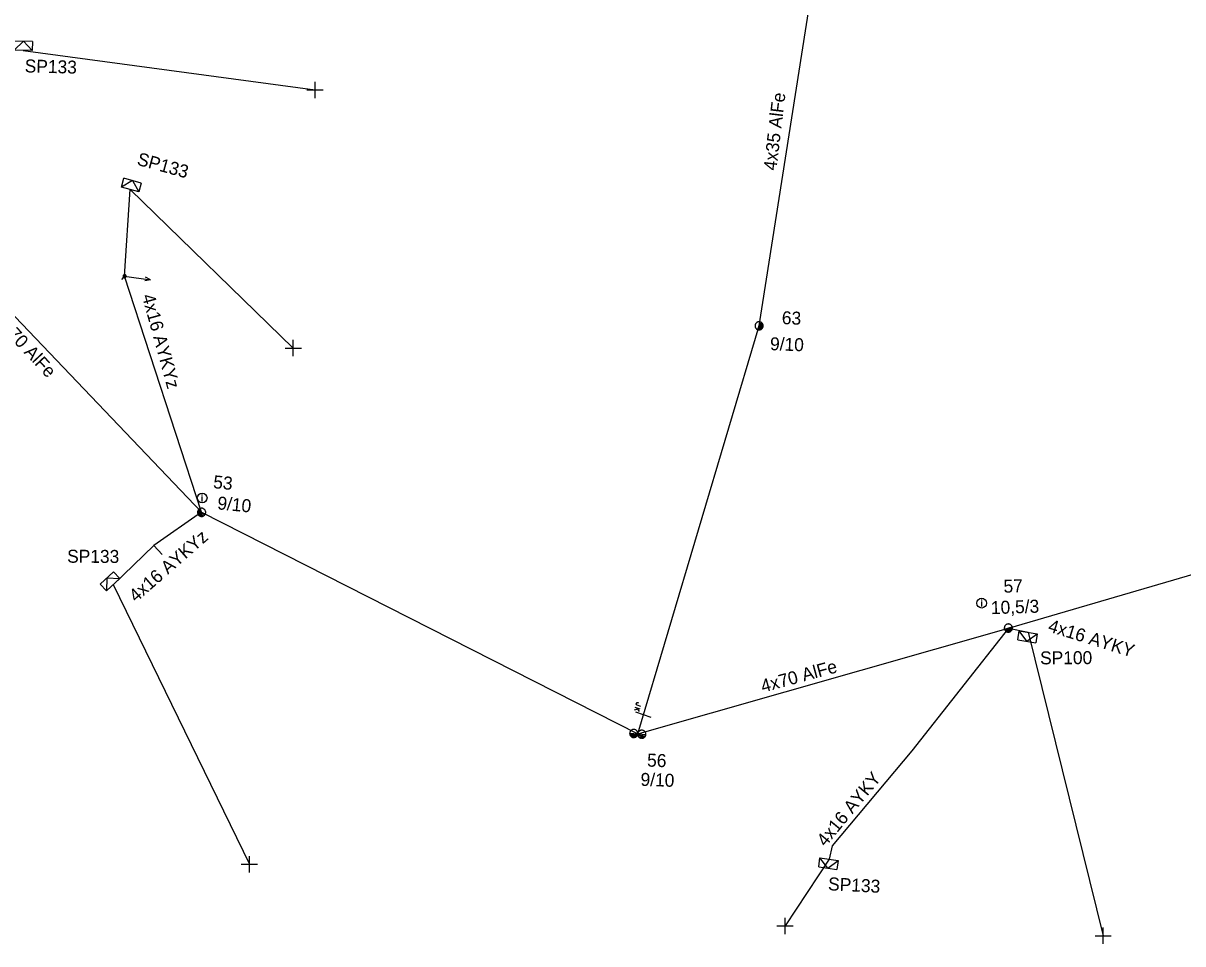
# Model space of a CAD drawing. Extents: x -748492 to -735633, y -1146251 to -1139940.
# Drawn here: x -739954.6 to -739865.3, y -1142153.9 to -1142083 of the extents above; entities that cross this region are included whole.
import ezdxf

# ---------------------------------------------------------------- set-up
doc = ezdxf.new("R2010")
doc.units = 0
for name, color, linetype in [('Vrstva 1', 7, 'Continuous'), ('Vrstva 10', 7, 'Continuous'), ('Vrstva 12', 7, 'Continuous'), ('Vrstva 13', 7, 'Continuous'), ('Vrstva 14', 7, 'Continuous'), ('Vrstva 15', 7, 'Continuous'), ('Vrstva 18', 7, 'Continuous'), ('Vrstva 2', 7, 'Continuous'), ('Vrstva 31', 7, 'Continuous'), ('Vrstva 33', 7, 'Continuous'), ('Vrstva 34', 7, 'Continuous'), ('Vrstva 36', 7, 'Continuous'), ('Vrstva 52', 7, 'Continuous'), ('Vrstva 54', 7, 'Continuous'), ('Vrstva 55', 7, 'Continuous'), ('Vrstva 59', 7, 'Continuous'), ('Vrstva 9', 7, 'Continuous')]:
    doc.layers.add(name, color=color, linetype=linetype)

# ---------------------------------------------------------------- blocks, each defined once
blk = doc.blocks.new('NN440')
at = {"layer": 'Vrstva 2'}
for points in [[(0.63, 0), (0.63, 0.06), (0.62, 0.13), (0.6, 0.19), (0.58, 0.25), (0.55, 0.31), (0.51, 0.37), (0.47, 0.42), (0.42, 0.46), (0.37, 0.51), (0.32, 0.54), (0.26, 0.57), (0.2, 0.59), (0.13, 0.61), (0.07, 0.62), (0, 0.63), (-0.06, 0.62), (-0.13, 0.61), (-0.19, 0.59), (-0.26, 0.57), (-0.31, 0.54), (-0.37, 0.51), (-0.42, 0.46), (-0.47, 0.42), (-0.51, 0.37), (-0.54, 0.31), (-0.57, 0.25), (-0.6, 0.19), (-0.62, 0.13), (-0.63, 0.06), (-0.63, 0), (-0.63, -0.07), (-0.62, -0.14), (-0.6, -0.2), (-0.57, -0.26), (-0.54, -0.32), (-0.51, -0.37), (-0.47, -0.43), (-0.42, -0.47), (-0.37, -0.51), (-0.31, -0.55), (-0.26, -0.58), (-0.19, -0.6), (-0.13, -0.62), (-0.06, -0.63), (0, -0.63), (0.07, -0.63), (0.13, -0.62), (0.2, -0.6), (0.26, -0.58), (0.32, -0.55), (0.37, -0.51), (0.42, -0.47), (0.47, -0.43), (0.51, -0.37), (0.55, -0.32), (0.58, -0.26), (0.6, -0.2), (0.62, -0.14), (0.63, -0.07), (0.63, 0)], [(-0.63, 0), (0.63, 0)], [(-0.6, -0.18), (0.57, -0.18)], [(-0.51, -0.32), (0.5, -0.32)], [(-0.37, -0.47), (0.35, -0.47)]]:
    blk.add_lwpolyline(points, dxfattribs=at)
blk = doc.blocks.new('NN450')
at = {"layer": 'Vrstva 2'}
for points in [[(0, 0), (0, 0.07), (-0.01, 0.13), (-0.03, 0.19), (-0.05, 0.25), (-0.08, 0.31), (-0.12, 0.37), (-0.16, 0.42), (-0.21, 0.46), (-0.26, 0.51), (-0.31, 0.54), (-0.37, 0.57), (-0.43, 0.59), (-0.5, 0.61), (-0.56, 0.62), (-0.63, 0.62), (-0.69, 0.62), (-0.75, 0.61), (-0.82, 0.59), (-0.88, 0.57), (-0.94, 0.54), (-0.99, 0.51), (-1.04, 0.46), (-1.09, 0.42), (-1.13, 0.37), (-1.17, 0.31), (-1.2, 0.25), (-1.22, 0.19), (-1.24, 0.13), (-1.25, 0.07), (-1.25, 0), (-1.25, -0.07), (-1.24, -0.13), (-1.22, -0.19), (-1.2, -0.25), (-1.17, -0.31), (-1.13, -0.37), (-1.09, -0.42), (-1.04, -0.46), (-0.99, -0.51), (-0.94, -0.54), (-0.88, -0.57), (-0.82, -0.59), (-0.75, -0.61), (-0.69, -0.62), (-0.62, -0.63), (-0.56, -0.62), (-0.5, -0.61), (-0.43, -0.59), (-0.37, -0.57), (-0.31, -0.54), (-0.26, -0.51), (-0.21, -0.46), (-0.16, -0.42), (-0.12, -0.37), (-0.08, -0.31), (-0.05, -0.25), (-0.03, -0.19), (-0.01, -0.13), (0, -0.07), (0, 0)], [(1.25, 0), (1.25, 0.07), (1.24, 0.13), (1.22, 0.19), (1.2, 0.25), (1.17, 0.31), (1.13, 0.37), (1.09, 0.42), (1.04, 0.46), (0.99, 0.51), (0.94, 0.54), (0.88, 0.57), (0.82, 0.59), (0.75, 0.61), (0.69, 0.62), (0.62, 0.62), (0.56, 0.62), (0.5, 0.61), (0.43, 0.59), (0.37, 0.57), (0.31, 0.54), (0.26, 0.51), (0.21, 0.46), (0.16, 0.42), (0.12, 0.37), (0.08, 0.31), (0.05, 0.25), (0.03, 0.19), (0.01, 0.13), (0, 0.07), (0, 0), (0, -0.07), (0.01, -0.13), (0.03, -0.19), (0.05, -0.25), (0.08, -0.31), (0.12, -0.37), (0.16, -0.42), (0.21, -0.46), (0.26, -0.51), (0.31, -0.54), (0.37, -0.57), (0.43, -0.59), (0.5, -0.61), (0.56, -0.62), (0.63, -0.63), (0.69, -0.62), (0.75, -0.61), (0.82, -0.59), (0.88, -0.57), (0.94, -0.54), (0.99, -0.51), (1.04, -0.46), (1.09, -0.42), (1.13, -0.37), (1.17, -0.31), (1.2, -0.25), (1.22, -0.19), (1.24, -0.13), (1.25, -0.07), (1.25, 0)], [(-1.25, 0), (1.25, 0)], [(-1.23, -0.16), (-0.02, -0.16)], [(-1.16, -0.32), (-0.09, -0.32)], [(-1.03, -0.47), (-0.22, -0.47)], [(0.02, -0.16), (1.23, -0.16)], [(0.09, -0.32), (1.16, -0.32)], [(0.22, -0.47), (1.03, -0.47)]]:
    blk.add_lwpolyline(points, dxfattribs=at)
blk = doc.blocks.new('NN560')
at = {"layer": 'Vrstva 2'}
for points in [[(1.999, -0.001), (1.59, 0.141)], [(0, -0.001), (1.999, -0.001)], [(1.999, -0.001), (1.59, -0.134)]]:
    blk.add_lwpolyline(points, dxfattribs=at)
blk = doc.blocks.new('NN840')
at = {"layer": 'Vrstva 15'}
for points in [[(0.003, 0.619), (0.003, -0.631)], [(-0.745, -0.71), (-0.745, -0.66)], [(-0.73, -0.764), (-0.745, -0.71)], [(-0.657, -0.798), (-0.73, -0.764)], [(-0.627, -0.798), (-0.657, -0.798)], [(-0.558, -0.764), (-0.627, -0.798)], [(-0.538, -0.71), (-0.558, -0.764)], [(-0.538, -0.385), (-0.538, -0.71)], [(-0.332, -0.385), (-0.332, -0.798)], [(-0.332, -0.641), (-0.125, -0.385)], [(-0.263, -0.557), (-0.091, -0.798)]]:
    blk.add_lwpolyline(points, dxfattribs=at)
blk = doc.blocks.new('NN770')
at = {"layer": 'Vrstva 10'}
for p, q in [((0.002, 0.187), (0.002, 0.263)), ((0.002, -0.276), (0.002, 0.111))]:
    blk.add_line(p, q, dxfattribs=at)
blk.add_circle((0, -0.008), 0.375, dxfattribs=at)
blk = doc.blocks.new('NN800')
at = {"layer": 'Vrstva 1'}
for points in [[(-0.442, 0.442), (0.442, -0.442)], [(-0.442, -0.442), (0.442, 0.442)]]:
    blk.add_lwpolyline(points, dxfattribs=at)
blk = doc.blocks.new('NN630')
at = {"layer": 'Vrstva 9'}
for points in [[(-0.003, -0.7), (-0.703, 0)], [(-0.703, -0.7), (-0.703, 0), (0.697, 0), (0.697, -0.7)], [(-0.703, -0.7), (0.697, -0.7)], [(-0.003, -0.7), (0.697, 0)]]:
    blk.add_lwpolyline(points, dxfattribs=at)
blk = doc.blocks.new('NN500')
at = {"layer": 'Vrstva 2'}
for points in [[(0, -0.24), (0.02, -0.23), (0.05, -0.23), (0.07, -0.22), (0.09, -0.22), (0.12, -0.2), (0.14, -0.19), (0.16, -0.18), (0.17, -0.16), (0.19, -0.14), (0.2, -0.12), (0.21, -0.1), (0.22, -0.07), (0.23, -0.05), (0.23, -0.02), (0.23, 0), (0.23, 0.02), (0.23, 0.05), (0.22, 0.07), (0.21, 0.1), (0.2, 0.12), (0.19, 0.14), (0.17, 0.16), (0.16, 0.17), (0.14, 0.19), (0.12, 0.2), (0.09, 0.21), (0.07, 0.22), (0.05, 0.23), (0.02, 0.23), (0, 0.23), (-0.03, 0.23), (-0.05, 0.23), (-0.07, 0.22), (-0.1, 0.21), (-0.12, 0.2), (-0.14, 0.19), (-0.16, 0.17), (-0.18, 0.16), (-0.19, 0.14), (-0.2, 0.12), (-0.22, 0.1), (-0.22, 0.07), (-0.23, 0.05), (-0.23, 0.02), (-0.24, 0), (-0.23, -0.02), (-0.23, -0.05), (-0.22, -0.07), (-0.22, -0.1), (-0.2, -0.12), (-0.19, -0.14), (-0.18, -0.16), (-0.16, -0.18), (-0.14, -0.19), (-0.12, -0.2), (-0.1, -0.22), (-0.07, -0.22), (-0.05, -0.23), (-0.03, -0.23), (0, -0.24)], [(0, -0.24), (0.02, -0.23), (0.05, -0.23), (0.07, -0.22), (0.09, -0.22), (0.12, -0.2), (0.14, -0.19), (0.16, -0.18), (0.17, -0.16), (0.19, -0.14), (0.2, -0.12), (0.21, -0.1), (0.22, -0.07), (0.23, -0.05), (0.23, -0.02), (0.23, 0), (0.23, 0.02), (0.23, 0.05), (0.22, 0.07), (0.21, 0.1), (0.2, 0.12), (0.19, 0.14), (0.17, 0.16), (0.16, 0.17), (0.14, 0.19), (0.12, 0.2), (0.09, 0.21), (0.07, 0.22), (0.05, 0.23), (0.02, 0.23), (0, 0.23), (-0.03, 0.23), (-0.05, 0.23), (-0.07, 0.22), (-0.1, 0.21), (-0.12, 0.2), (-0.14, 0.19), (-0.16, 0.17), (-0.18, 0.16), (-0.19, 0.14), (-0.2, 0.12), (-0.22, 0.1), (-0.22, 0.07), (-0.23, 0.05), (-0.23, 0.02), (-0.24, 0), (-0.23, -0.02), (-0.23, -0.05), (-0.22, -0.07), (-0.22, -0.1), (-0.2, -0.12), (-0.19, -0.14), (-0.18, -0.16), (-0.16, -0.18), (-0.14, -0.19), (-0.12, -0.2), (-0.1, -0.22), (-0.07, -0.22), (-0.05, -0.23), (-0.03, -0.23), (0, -0.24)], [(0, -0.21), (0.02, -0.2), (0.04, -0.2), (0.06, -0.2), (0.08, -0.19), (0.1, -0.18), (0.12, -0.17), (0.14, -0.15), (0.15, -0.14), (0.16, -0.12), (0.18, -0.1), (0.19, -0.08), (0.19, -0.06), (0.2, -0.04), (0.2, -0.02), (0.2, 0), (0.2, 0.02), (0.2, 0.04), (0.19, 0.06), (0.19, 0.08), (0.18, 0.1), (0.16, 0.12), (0.15, 0.14), (0.14, 0.15), (0.12, 0.17), (0.1, 0.18), (0.08, 0.19), (0.06, 0.19), (0.04, 0.2), (0.02, 0.2), (0, 0.2), (-0.02, 0.2), (-0.04, 0.2), (-0.06, 0.19), (-0.08, 0.19), (-0.1, 0.18), (-0.12, 0.17), (-0.14, 0.15), (-0.15, 0.14), (-0.17, 0.12), (-0.18, 0.1), (-0.19, 0.08), (-0.2, 0.06), (-0.2, 0.04), (-0.21, 0.02), (-0.21, 0), (-0.21, -0.02), (-0.2, -0.04), (-0.2, -0.06), (-0.19, -0.08), (-0.18, -0.1), (-0.17, -0.12), (-0.15, -0.14), (-0.14, -0.15), (-0.12, -0.17), (-0.1, -0.18), (-0.08, -0.19), (-0.06, -0.2), (-0.04, -0.2), (-0.02, -0.2), (0, -0.21)], [(0, -0.18), (0.02, -0.18), (0.04, -0.17), (0.05, -0.17), (0.07, -0.16), (0.09, -0.15), (0.1, -0.14), (0.12, -0.13), (0.13, -0.12), (0.14, -0.1), (0.15, -0.09), (0.16, -0.07), (0.17, -0.05), (0.17, -0.04), (0.17, -0.02), (0.17, 0), (0.17, 0.02), (0.17, 0.04), (0.17, 0.05), (0.16, 0.07), (0.15, 0.09), (0.14, 0.1), (0.13, 0.12), (0.12, 0.13), (0.1, 0.14), (0.09, 0.15), (0.07, 0.16), (0.05, 0.17), (0.04, 0.17), (0.02, 0.17), (0, 0.18), (-0.02, 0.17), (-0.04, 0.17), (-0.06, 0.17), (-0.07, 0.16), (-0.09, 0.15), (-0.1, 0.14), (-0.12, 0.13), (-0.13, 0.12), (-0.14, 0.1), (-0.15, 0.09), (-0.16, 0.07), (-0.17, 0.05), (-0.17, 0.04), (-0.18, 0.02), (-0.18, 0), (-0.18, -0.02), (-0.17, -0.04), (-0.17, -0.05), (-0.16, -0.07), (-0.15, -0.09), (-0.14, -0.1), (-0.13, -0.12), (-0.12, -0.13), (-0.1, -0.14), (-0.09, -0.15), (-0.07, -0.16), (-0.06, -0.17), (-0.04, -0.17), (-0.02, -0.18), (0, -0.18)], [(0, -0.15), (0.01, -0.15), (0.03, -0.14), (0.04, -0.14), (0.06, -0.13), (0.07, -0.13), (0.08, -0.12), (0.1, -0.11), (0.11, -0.1), (0.12, -0.09), (0.13, -0.07), (0.13, -0.06), (0.14, -0.05), (0.14, -0.03), (0.14, -0.02), (0.14, 0), (0.14, 0.01), (0.14, 0.03), (0.14, 0.04), (0.13, 0.06), (0.13, 0.07), (0.12, 0.09), (0.11, 0.1), (0.1, 0.11), (0.08, 0.12), (0.07, 0.13), (0.06, 0.13), (0.04, 0.14), (0.03, 0.14), (0.01, 0.14), (0, 0.15), (-0.02, 0.14), (-0.03, 0.14), (-0.05, 0.14), (-0.06, 0.13), (-0.07, 0.13), (-0.09, 0.12), (-0.1, 0.11), (-0.11, 0.1), (-0.12, 0.09), (-0.13, 0.07), (-0.13, 0.06), (-0.14, 0.04), (-0.14, 0.03), (-0.15, 0.01), (-0.15, 0), (-0.15, -0.02), (-0.14, -0.03), (-0.14, -0.05), (-0.13, -0.06), (-0.13, -0.07), (-0.12, -0.09), (-0.11, -0.1), (-0.1, -0.11), (-0.09, -0.12), (-0.07, -0.13), (-0.06, -0.13), (-0.05, -0.14), (-0.03, -0.14), (-0.02, -0.15), (0, -0.15)], [(0, -0.12), (0.01, -0.12), (0.02, -0.11), (0.03, -0.11), (0.05, -0.11), (0.06, -0.1), (0.07, -0.09), (0.08, -0.09), (0.09, -0.08), (0.09, -0.07), (0.1, -0.06), (0.11, -0.05), (0.11, -0.04), (0.11, -0.02), (0.11, -0.01), (0.12, 0), (0.11, 0.01), (0.11, 0.02), (0.11, 0.04), (0.11, 0.05), (0.1, 0.06), (0.09, 0.07), (0.09, 0.08), (0.08, 0.09), (0.07, 0.09), (0.06, 0.1), (0.05, 0.11), (0.03, 0.11), (0.02, 0.11), (0.01, 0.12), (0, 0.12), (-0.01, 0.12), (-0.03, 0.11), (-0.04, 0.11), (-0.05, 0.11), (-0.06, 0.1), (-0.07, 0.09), (-0.08, 0.09), (-0.09, 0.08), (-0.1, 0.07), (-0.1, 0.06), (-0.11, 0.05), (-0.11, 0.04), (-0.12, 0.02), (-0.12, 0.01), (-0.12, 0), (-0.12, -0.01), (-0.12, -0.02), (-0.11, -0.04), (-0.11, -0.05), (-0.1, -0.06), (-0.1, -0.07), (-0.09, -0.08), (-0.08, -0.09), (-0.07, -0.09), (-0.06, -0.1), (-0.05, -0.11), (-0.04, -0.11), (-0.03, -0.11), (-0.01, -0.12), (0, -0.12)], [(0, -0.09), (0.01, -0.09), (0.02, -0.09), (0.03, -0.08), (0.03, -0.08), (0.04, -0.08), (0.05, -0.07), (0.06, -0.07), (0.06, -0.06), (0.07, -0.05), (0.07, -0.04), (0.08, -0.04), (0.08, -0.03), (0.08, -0.02), (0.09, -0.01), (0.09, 0), (0.09, 0.01), (0.08, 0.02), (0.08, 0.03), (0.08, 0.03), (0.07, 0.04), (0.07, 0.05), (0.06, 0.06), (0.06, 0.06), (0.05, 0.07), (0.04, 0.07), (0.03, 0.08), (0.03, 0.08), (0.02, 0.08), (0.01, 0.09), (0, 0.09), (-0.01, 0.09), (-0.02, 0.08), (-0.03, 0.08), (-0.04, 0.08), (-0.04, 0.07), (-0.05, 0.07), (-0.06, 0.06), (-0.07, 0.06), (-0.07, 0.05), (-0.08, 0.04), (-0.08, 0.03), (-0.08, 0.03), (-0.09, 0.02), (-0.09, 0.01), (-0.09, 0), (-0.09, -0.01), (-0.09, -0.02), (-0.08, -0.03), (-0.08, -0.04), (-0.08, -0.04), (-0.07, -0.05), (-0.07, -0.06), (-0.06, -0.07), (-0.05, -0.07), (-0.04, -0.08), (-0.04, -0.08), (-0.03, -0.08), (-0.02, -0.09), (-0.01, -0.09), (0, -0.09)], [(0, -0.06), (0, -0.06), (0.01, -0.06), (0.02, -0.05), (0.02, -0.05), (0.03, -0.05), (0.03, -0.05), (0.04, -0.04), (0.04, -0.04), (0.05, -0.03), (0.05, -0.03), (0.05, -0.02), (0.05, -0.02), (0.05, -0.01), (0.06, -0.01), (0.06, 0), (0.06, 0.01), (0.05, 0.01), (0.05, 0.02), (0.05, 0.02), (0.05, 0.03), (0.05, 0.03), (0.04, 0.04), (0.04, 0.04), (0.03, 0.05), (0.03, 0.05), (0.02, 0.05), (0.02, 0.05), (0.01, 0.06), (0, 0.06), (0, 0.06), (-0.01, 0.06), (-0.01, 0.06), (-0.02, 0.05), (-0.02, 0.05), (-0.03, 0.05), (-0.03, 0.05), (-0.04, 0.04), (-0.04, 0.04), (-0.05, 0.03), (-0.05, 0.03), (-0.05, 0.02), (-0.06, 0.02), (-0.06, 0.01), (-0.06, 0.01), (-0.06, 0), (-0.06, -0.01), (-0.06, -0.01), (-0.06, -0.02), (-0.05, -0.02), (-0.05, -0.03), (-0.05, -0.03), (-0.04, -0.04), (-0.04, -0.04), (-0.03, -0.05), (-0.03, -0.05), (-0.02, -0.05), (-0.02, -0.05), (-0.01, -0.06), (-0.01, -0.06), (0, -0.06)], [(0, -0.03), (0, -0.03), (0, -0.03), (0.01, -0.03), (0.01, -0.03), (0.01, -0.02), (0.02, -0.02), (0.02, -0.02), (0.02, -0.02), (0.02, -0.02), (0.02, -0.01), (0.02, -0.01), (0.03, -0.01), (0.03, -0.01), (0.03, 0), (0.03, 0), (0.03, 0), (0.03, 0.01), (0.03, 0.01), (0.02, 0.01), (0.02, 0.01), (0.02, 0.02), (0.02, 0.02), (0.02, 0.02), (0.02, 0.02), (0.01, 0.02), (0.01, 0.02), (0.01, 0.03), (0, 0.03), (0, 0.03), (0, 0.03), (0, 0.03), (-0.01, 0.03), (-0.01, 0.03), (-0.01, 0.02), (-0.02, 0.02), (-0.02, 0.02), (-0.02, 0.02), (-0.02, 0.02), (-0.02, 0.02), (-0.03, 0.01), (-0.03, 0.01), (-0.03, 0.01), (-0.03, 0.01), (-0.03, 0), (-0.03, 0), (-0.03, 0), (-0.03, -0.01), (-0.03, -0.01), (-0.03, -0.01), (-0.03, -0.01), (-0.02, -0.02), (-0.02, -0.02), (-0.02, -0.02), (-0.02, -0.02), (-0.02, -0.02), (-0.01, -0.03), (-0.01, -0.03), (-0.01, -0.03), (0, -0.03), (0, -0.03)], [(0.23, 0), (0.7, 0)]]:
    blk.add_lwpolyline(points, dxfattribs=at)
blk = doc.blocks.new('NN510')
at = {"layer": 'Vrstva 2'}
blk.add_lwpolyline([(0.001, 0.002), (0.001, 0.939)], dxfattribs=at)

msp = doc.modelspace()

# ---------------------------------------------------------------- linework, layer by layer
at = {"layer": 'Vrstva 1'}
for points in [[(-739976.31, -1142041.09), (-739968.81, -1142075.35), (-739965.36, -1142094.99), (-739940.87, -1142120.65), (-739907.28, -1142137.71)], [(-739907.28, -1142137.71), (-739897.94, -1142106.29), (-739892.53, -1142071.94), (-739878.26, -1142057.14), (-739869.72, -1142047.78)], [(-739907.28, -1142137.71), (-739878.74, -1142129.56), (-739857.833, -1142123.466), (-739855.41, -1142122.76)]]:
    msp.add_lwpolyline(points, dxfattribs=at)
at = {"layer": 'Vrstva 52'}
for points in [[(-739878.74, -1142129.56), (-739886.16, -1142139.01), (-739892.3, -1142146.34), (-739892.55, -1142147.36)], [(-739878.74, -1142129.56), (-739877.211, -1142129.89)]]:
    msp.add_lwpolyline(points, dxfattribs=at)
at = {"layer": 'Vrstva 54'}
for points in [[(-739940.87, -1142120.65), (-739946.8, -1142102.47), (-739946.378, -1142095.784)], [(-739940.87, -1142120.65), (-739944.56, -1142123.21), (-739947.69, -1142126.221)]]:
    msp.add_lwpolyline(points, dxfattribs=at)
at = {"layer": 'Vrstva 59'}
for points in [[(-739954.612, -1142085.077), (-739932.13, -1142088.13)], [(-739946.377, -1142095.784), (-739933.81, -1142108)], [(-739947.691, -1142126.22), (-739937.19, -1142147.75)], [(-739877.21, -1142129.89), (-739871.44, -1142153.25)], [(-739892.55, -1142147.36), (-739895.94, -1142152.5)]]:
    msp.add_lwpolyline(points, dxfattribs=at)

# ---------------------------------------------------------------- block references
at = {"layer": 'Vrstva 13'}
for name, p, xscale, yscale, rotation in [('NN500', (-739946.8, -1142102.469), 0.5, 0.5, -134.067001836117), ('NN440', (-739897.939, -1142106.29), 0.49999999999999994, 0.5000000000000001, 71.7726250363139), ('NN440', (-739940.87, -1142120.65), 0.5, 0.5, -46.9718166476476), ('NN440', (-739878.74, -1142129.56), 0.5, 0.5, 15.3051388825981), ('NN450', (-739907.279, -1142137.71), 0.5, 0.5, -5.576525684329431)]:
    msp.add_blockref(name, p, dxfattribs=dict(at, xscale=xscale, yscale=yscale, rotation=rotation))
for name, p, rotation in [('NN560', (-739946.799, -1142102.471), -7.962833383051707), ('NN510', (-739944.559, -1142123.21), -136.5672059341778)]:
    msp.add_blockref(name, p, dxfattribs=dict(at, rotation=rotation))
at = {"layer": 'Vrstva 18', "rotation": -109.1648036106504}
msp.add_blockref('NN840', (-739906.844, -1142136.243), dxfattribs=at)
at = {"layer": 'Vrstva 31'}
for p, rotation in [((-739954.612, -1142085.077), 178.49858606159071), ((-739946.378, -1142095.784), 164.6426861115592), ((-739947.69, -1142126.22), -136.97181669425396), ((-739877.21, -1142129.889), -8.829833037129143), ((-739892.549, -1142147.36), -7.7315683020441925)]:
    msp.add_blockref('NN630', p, dxfattribs=dict(at, rotation=rotation))
at = {"layer": 'Vrstva 34'}
for p, rotation in [((-739932.13, -1142088.13), 45), ((-739933.81, -1142108), 45), ((-739937.19, -1142147.75), 44.99999995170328), ((-739895.94, -1142152.5), 44.99999995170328), ((-739871.44, -1142153.25), 44.99999995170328)]:
    msp.add_blockref('NN800', p, dxfattribs=dict(at, rotation=rotation))
at = {"layer": 'Vrstva 36'}
for p in [(-739940.829, -1142119.537), (-739880.794, -1142127.635)]:
    msp.add_blockref('NN770', p, dxfattribs=at)

# ---------------------------------------------------------------- texts
at = {"layer": 'Vrstva 12'}
for s, rotation, p in [('9/10', 358.033, (-739897.106, -1142108.164)), ('9/10', 354.326, (-739939.693, -1142120.414)), ('10,5/3', 1.938, (-739880.065, -1142128.496)), ('9/10', 358.089, (-739907.079, -1142141.708))]:
    msp.add_text(s, height=1, rotation=rotation, dxfattribs=at).set_placement(p)
at = {"layer": 'Vrstva 14'}
for s, rotation, p in [('63', 358.033, (-739896.199, -1142106.159)), ('53', 354.326, (-739940.011, -1142118.787)), ('57', 1.938, (-739879.094, -1142126.848)), ('56', 358.089, (-739906.575, -1142140.227))]:
    msp.add_text(s, height=1, rotation=rotation, dxfattribs=at).set_placement(p)
at = {"layer": 'Vrstva 2'}
for s, rotation, p in [('4x35 AlFe', 83.223, (-739896.608, -1142094.364)), ('4x70 AlFe', 313.028, (-739956.832, -1142105.964)), ('4x70 AlFe', 15.305, (-739897.646, -1142134.539))]:
    msp.add_text(s, height=1, rotation=rotation, dxfattribs=at).set_placement(p)
at = {"layer": 'Vrstva 33'}
for s, rotation, p in [('SP133', 358.499, (-739954.505, -1142086.771)), ('SP133', 344.643, (-739945.913, -1142093.878)), ('SP133', 359.739, (-739951.23, -1142124.53)), ('SP100', 0.349, (-739876.291, -1142132.359)), ('SP133', 357.109, (-739892.64, -1142149.75))]:
    msp.add_text(s, height=1, rotation=rotation, dxfattribs=at).set_placement(p)
at = {"layer": 'Vrstva 54'}
for rotation, p in [(342.801, (-739875.746, -1142129.809)), (50.638, (-739892.822, -1142146.452))]:
    msp.add_text('4x16 AYKY', height=1, rotation=rotation, dxfattribs=at).set_placement(p)
at = {"layer": 'Vrstva 55'}
for rotation, p in [(285.389, (-739945.477, -1142103.986)), (41.183, (-739945.929, -1142127.619))]:
    msp.add_text('4x16 AYKYz', height=1, rotation=rotation, dxfattribs=at).set_placement(p)

doc.saveas('drawing.dxf')
